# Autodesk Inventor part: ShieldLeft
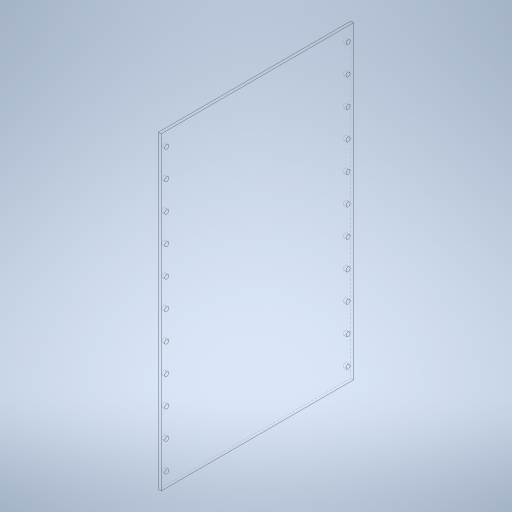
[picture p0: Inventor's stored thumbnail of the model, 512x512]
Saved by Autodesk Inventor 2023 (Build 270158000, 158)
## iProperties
Created: 2023-10
Part Number: ShieldLeft
Material: Aluminum 7075
Document SubType Name: Modeling
Designer: tornqvih
Density: 2.81 g/cm^3
Appearance: Satin - Brushed Heavy
Author: tornqvih
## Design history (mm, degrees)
sketch "Sketch1"
  geometry: L1 (110, 68.5)-(-110, 68.5); L2 (-110, 68.5)-(-110, -68.5); L3 (-110, -68.5)-(110, -68.5); L4 (110, -68.5)-(110, 68.5); L5 (110, 68.5)-(-110, -68.5); L6 (-110, 68.5)-(110, -68.5); 1 further point
  constraints: 12 end point, 2 midpoint, 2 parallel, 1 horizontal, 1 perpendicular
  dimensions: "d0" = 137 distance of L3.end L1.start; "d1" = 220 distance of L1.start L1.end
extrude "Extrusion1" new body sketch "Sketch1" distance "d2" = 2; taper "d3" = 0 deg
sketch "Sketch2"
  geometry: L1 (68.5, 110)-(-68.5, 110) reference; L2 (-68.5, 110)-(-68.5, -110) reference; L3 (0, -154)-(0, 154) reference; 25 further points; 1 other entity
  constraints: 11 vertical alignment, 10 symmetric about line, 2 other
  dimensions: "d5" = 4 distance from line of L2 point (-64.5, 100); "d13" = 20 dimension on point (-64.5, 20); "d14" = 60 dimension on point (-64.5, 60); "d15" = 100 dimension on point (-64.5, 100); "d16" = 40 dimension on point (-64.5, 40); "d17" = 80 dimension on point (-64.5, 80)
hole "Hole1" sketch "Sketch2" diameter "d6" = 3; stored, may be unused: countersink angle "d10" = 90 deg, drill point angle "d12" = 118 deg; dims "d7" = 6, "d8" = 4, "d9" = 2, "d11" = 8
body "Solid1"
